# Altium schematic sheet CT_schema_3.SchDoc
size 467 x 344 mm
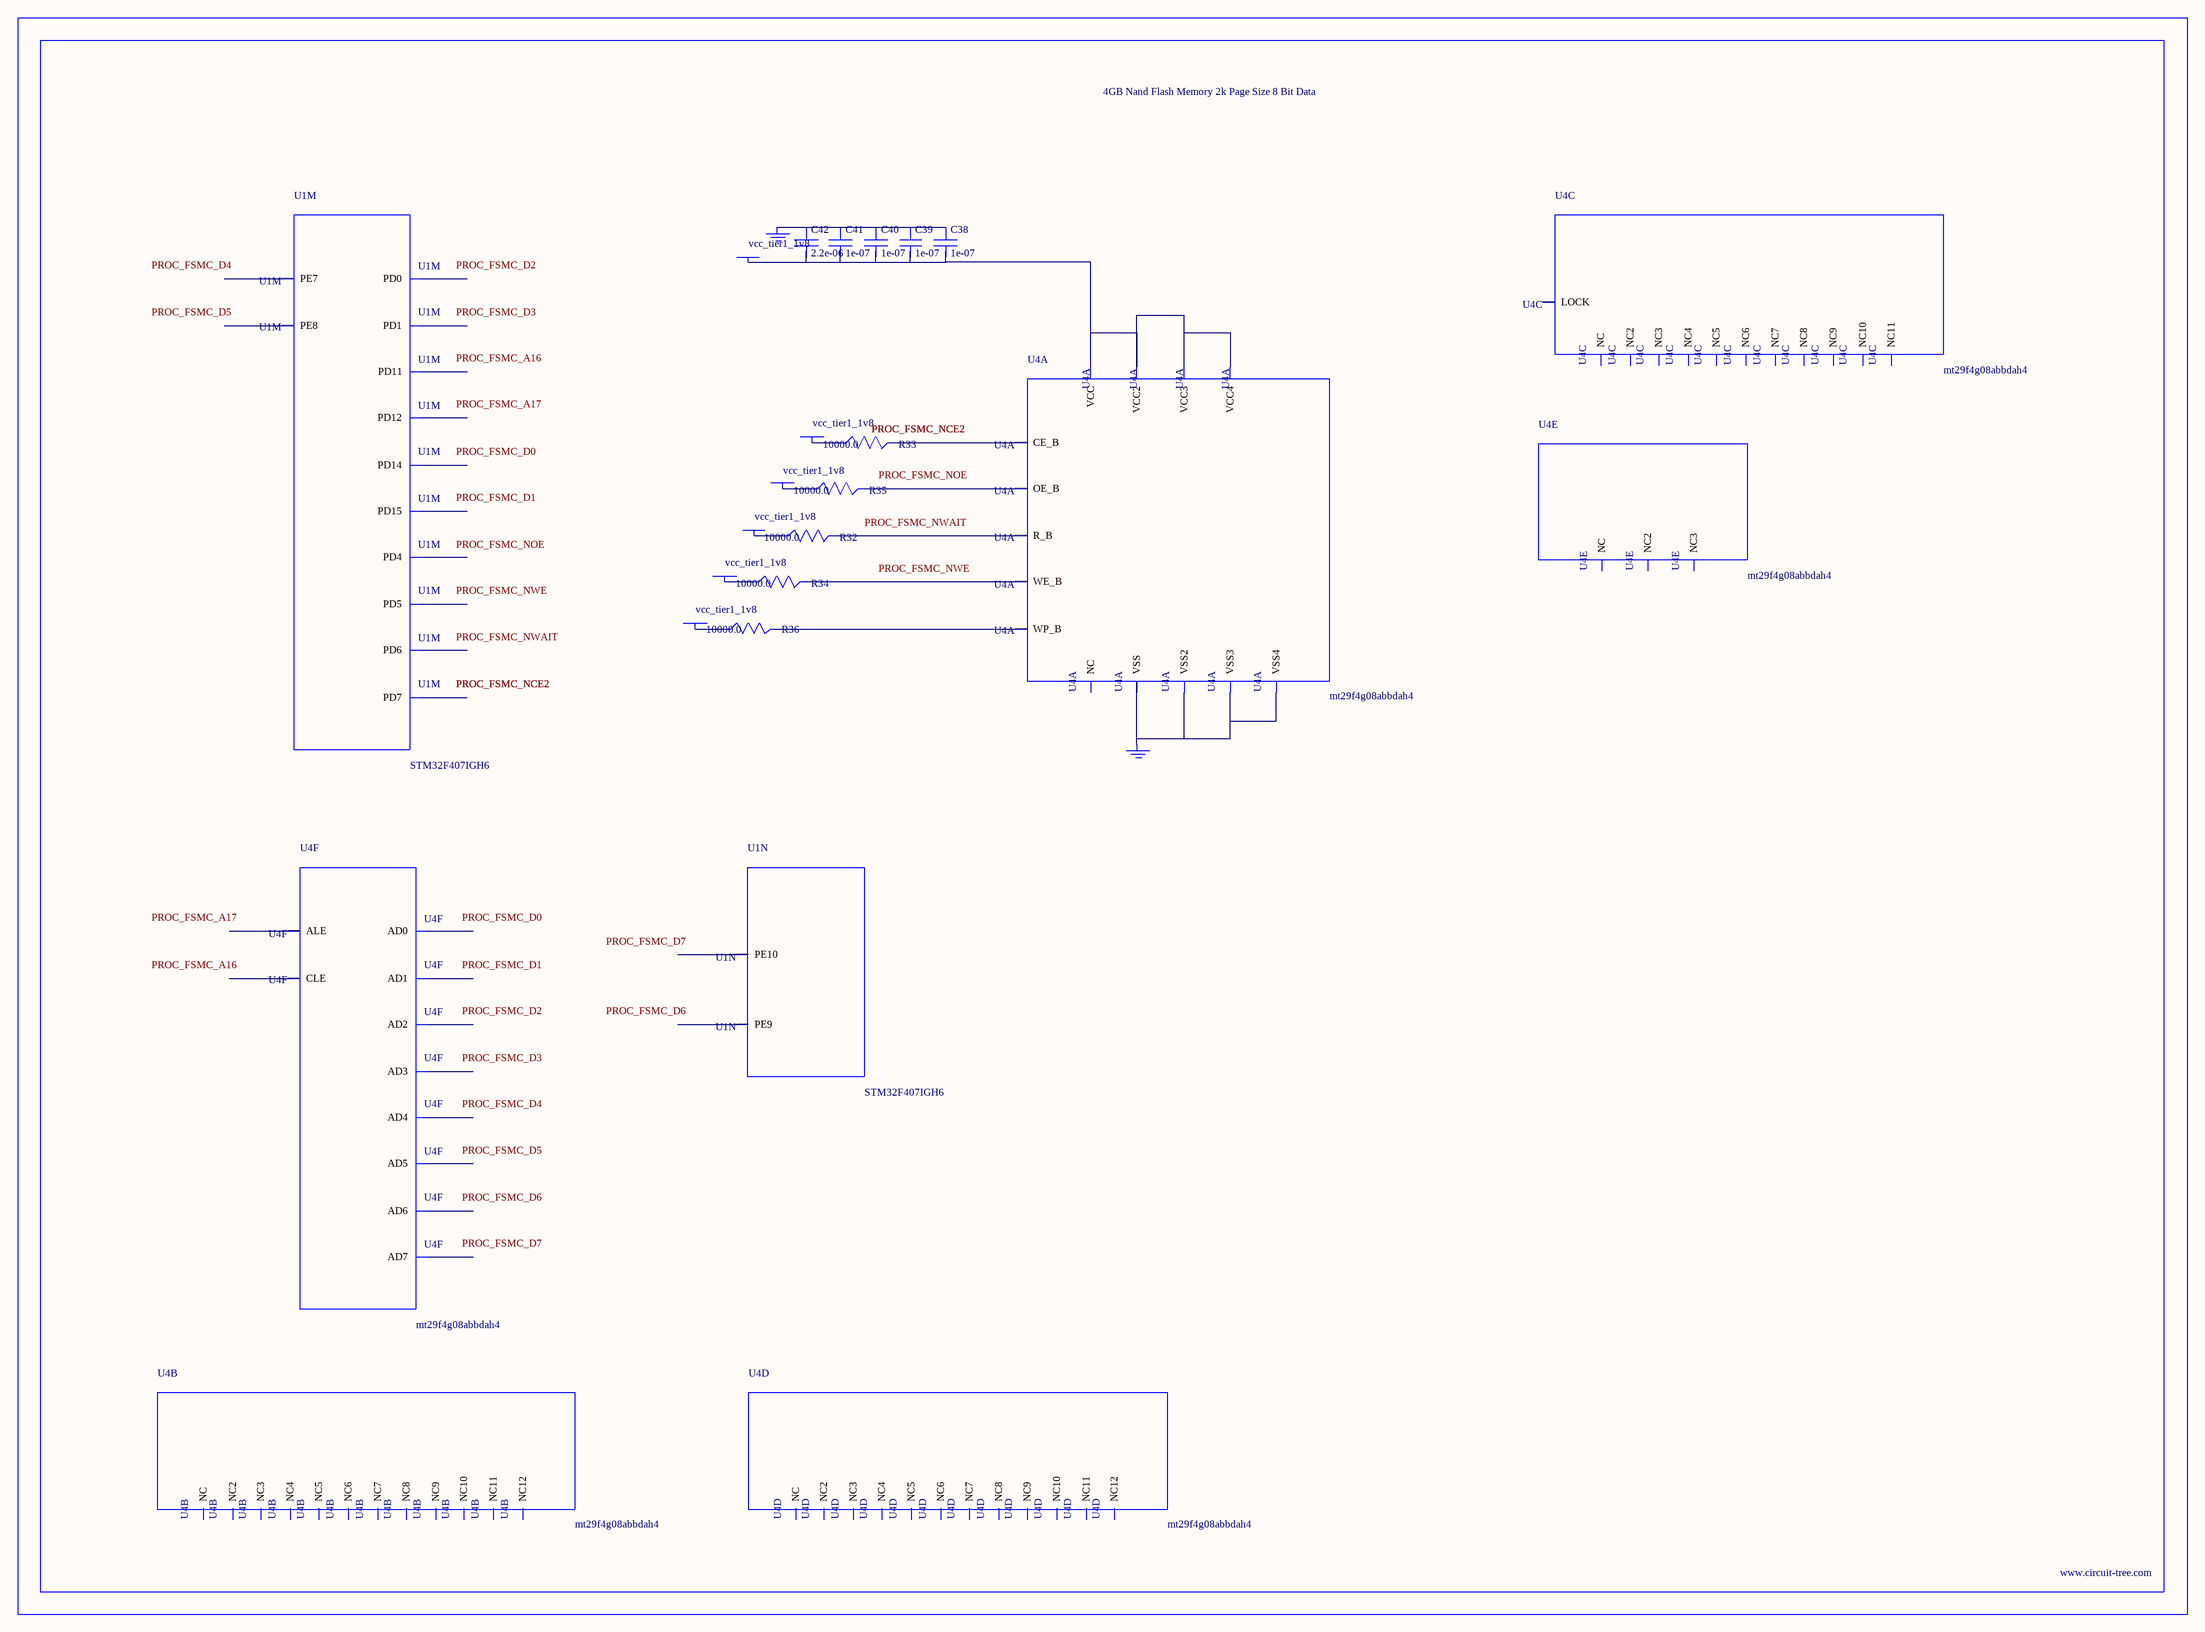
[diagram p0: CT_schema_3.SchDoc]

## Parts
BORDER2  (no value)
C38  1e-07  [C0402]
C39  1e-07  [C0402]
C40  1e-07  [C0402]
C41  1e-07  [C0402]
C42  2.2e-06  [C0603]
GND_INSTANCE_2_0  (no value)
GND_INSTANCE_2_1  (no value)
POWER_INSTANCE_2_0  vcc_tier1_1v8
POWER_INSTANCE_2_1  vcc_tier1_1v8
POWER_INSTANCE_2_2  vcc_tier1_1v8
POWER_INSTANCE_2_3  vcc_tier1_1v8
POWER_INSTANCE_2_4  vcc_tier1_1v8
POWER_INSTANCE_2_5  vcc_tier1_1v8
R32  10000.0  [R0603]
R33  10000.0  [R0603]
R34  10000.0  [R0603]
R35  10000.0  [R0603]
R36  10000.0  [R0603]
U1  STM32F407IGH6  [UFBGA176]  (parts M,N of 15)
U4  mt29f4g08abbdah4  [VFBGA-63]  (parts A,B,C,D,E,F of 6)

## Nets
NetC38_1: C38.1 C39.1 C40.1 C41.1 C42.1 GND_INSTANCE_2_0.0(GND)
NetC38_2: C38.2 C39.2 C40.2 C41.2 C42.2 POWER_INSTANCE_2_0.0(PWR) U4.D3(VCC) U4.G4(VCC2) U4.H8(VCC3) U4.J6(VCC4)
NetGND_INSTANCE_2_1_0: GND_INSTANCE_2_1.0(GND) U4.C5(VSS) U4.F7(VSS2) U4.K3(VSS3) U4.K8(VSS4)
NetPOWER_INSTANCE_2_1_0: POWER_INSTANCE_2_1.0(PWR) R32.1
NetPOWER_INSTANCE_2_2_0: POWER_INSTANCE_2_2.0(PWR) R33.1
NetPOWER_INSTANCE_2_3_0: POWER_INSTANCE_2_3.0(PWR) R34.1
NetPOWER_INSTANCE_2_4_0: POWER_INSTANCE_2_4.0(PWR) R35.1
NetPOWER_INSTANCE_2_5_0: POWER_INSTANCE_2_5.0(PWR) R36.1
NetR32_2: R32.2 U4.C8(R_B)
NetR33_2: R33.2 U4.C6(CE_B)
NetR34_2: R34.2 U4.C7(WE_B)
NetR35_2: R35.2 U4.D4(OE_B)
NetR36_2: R36.2 U4.C3(WP_B)

Not connected (* = marked no-connect by the designer): U1 A11(PD7) B11(PD6) B12(PD0) C11(PD5) C12(PD1) D10(PD4) L14(PD15) M14(PD14) N13(PD12) N14(PD11) P8(PE8) P9(PE9) R8(PE7) R9(PE10); U4 A1(NC) A2(NC3) A9(NC4) A10(NC2) B1(NC5) B9(NC7) B10(NC6) C4(ALE) D5(CLE) D6(NC8) D7(NC9) D8(NC10) E3(NC11) E4(NC12) E5(NC) E6(NC2) E7(NC3) E8(NC4) F3(NC5) F4(NC6) F5(NC7) F6(NC8) F8(NC9) G3(NC) G5(LOCK) G6(NC10) G7(NC11) G8(NC) H3(NC2) H4(AD0) H5(NC3) H6(NC4) H7(NC5) J3(NC6) J4(AD1) J5(NC7) J7(AD5) J8(AD7) K4(AD2) K5(AD3) K6(AD4) K7(AD6) L1(NC8) L2(NC10) L9(NC11) L10(NC9) M1(NC12) M2(NC2) M9(NC3) M10(NC)

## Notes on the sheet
- Labels drawn without touching a wire or pin: PROC_FSMC_A16, PROC_FSMC_A17, PROC_FSMC_D0, PROC_FSMC_D1, PROC_FSMC_D2, PROC_FSMC_D3, PROC_FSMC_D4, PROC_FSMC_D5, PROC_FSMC_D6, PROC_FSMC_D7, PROC_FSMC_NOE, PROC_FSMC_NWAIT, PROC_FSMC_NWE

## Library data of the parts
BORDER2 = BORDER_PAGE2
C38-C41 = C0402C104K3RACTU
C42 = C0603C225K8RACTU
GND_INSTANCE_2_0 GND_INSTANCE_2_1 = GND
POWER_INSTANCE_2_0-POWER_INSTANCE_2_5 = PWR
R32-R36 = RC0603JR-0710KL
